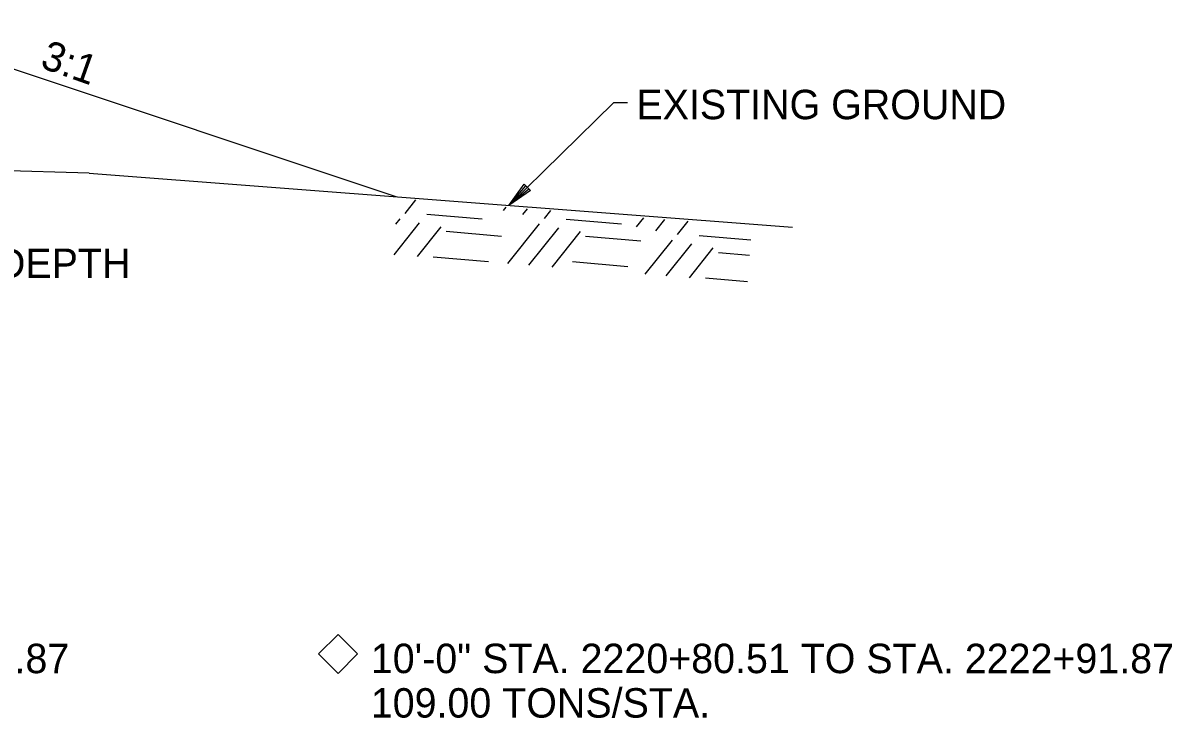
# Model space of a CAD drawing. Extents: x 1734743 to 1735935, y 759845 to 763831.
# Drawn here: x 1735860.28 to 1735907.1, y 760376.74 to 760405.08 of the extents above; entities that cross this region are included whole.
import ezdxf

# ---------------------------------------------------------------- set-up
doc = ezdxf.new("R2010")
doc.units = 0
doc.layers.add('10', color=7, linetype='Continuous')
doc.layers.add('19', color=7, linetype='Continuous')

msp = doc.modelspace()

# ---------------------------------------------------------------- linework, layer by layer
at = {"layer": '10'}
msp.add_lwpolyline([(1735873.122, 760380.149), (1735873.917, 760379.354), (1735873.122, 760378.558), (1735872.326, 760379.354)], close=True, dxfattribs=at)
at = {"layer": '19'}
for p, q in [((1735875.49, 760397.992), (1735854.232, 760405.077)), ((1735862.979, 760398.949), (1735843.15, 760399.58)), ((1735880.083, 760397.64), (1735880.705, 760398.506)), ((1735880.267, 760397.85), (1735880.766, 760398.436)), ((1735880.705, 760398.506), (1735880.958, 760398.244)), ((1735875.855, 760397.312), (1735876.29, 760397.861)), ((1735880.958, 760398.244), (1735880.083, 760397.64)), ((1735880.897, 760398.305), (1735880.302, 760397.815)), ((1735879.862, 760397.428), (1735879.977, 760397.573)), ((1735880.649, 760397.274), (1735880.835, 760397.507)), ((1735881.53, 760397.112), (1735881.784, 760397.433)), ((1735875.403, 760395.628), (1735876.439, 760396.932)), ((1735875.479, 760396.869), (1735875.651, 760397.086)), ((1735876.745, 760397.28), (1735878.998, 760397.086)), ((1735882.42, 760397.08), (1735884.673, 760396.886)), ((1735885.277, 760396.764), (1735885.574, 760397.137)), ((1735886.065, 760396.61), (1735886.431, 760397.071)), ((1735886.945, 760396.448), (1735887.381, 760396.997)), ((1735876.353, 760395.554), (1735877.319, 760396.77)), ((1735877.528, 760396.587), (1735879.781, 760396.392)), ((1735880.04, 760395.267), (1735881.326, 760396.886)), ((1735880.897, 760395.2), (1735882.114, 760396.732)), ((1735881.847, 760395.126), (1735882.994, 760396.57)), ((1735883.202, 760396.386), (1735885.456, 760396.192)), ((1735885.636, 760394.831), (1735886.742, 760396.222)), ((1735886.494, 760394.764), (1735887.529, 760396.068)), ((1735887.835, 760396.416), (1735889.933, 760396.235)), ((1735877, 760395.549), (1735879.254, 760395.355)), ((1735887.443, 760394.69), (1735888.409, 760395.906)), ((1735888.618, 760395.723), (1735889.885, 760395.613)), ((1735882.675, 760395.348), (1735884.929, 760395.154)), ((1735888.091, 760394.685), (1735889.801, 760394.537))]:
    msp.add_line(p, q, dxfattribs=at)
for points in [[(1735884.908, 760401.816), (1735884.339, 760401.816), (1735880.083, 760397.64)], [(1735862.979, 760398.949), (1735891.643, 760396.755)]]:
    msp.add_lwpolyline(points, dxfattribs=at)

# ---------------------------------------------------------------- texts
for s, rotation, p in [('3:1', 340.4943, (1735860.938, 760403.274)), ('(CLASS 7) - VAR. COMPACTED DEPTH', 360, (1735835.238, 760394.68)), ('VAR. FROM STA. 2220+80.51 TO STA. 2222+91.87', 359.9954, (1735824.618, 760378.573)), ('10\'-0" STA. 2220+80.51 TO STA. 2222+91.87', 359.9954, (1735874.457, 760378.573)), ('109.00 TONS/STA.', 359.9954, (1735874.457, 760376.76))]:
    msp.add_text(s, height=1.2, rotation=rotation, dxfattribs=at).set_placement(p)
msp.add_text('EXISTING GROUND', height=1.2, dxfattribs=at).set_placement((1735885.276, 760401.154))

doc.saveas('drawing.dxf')
